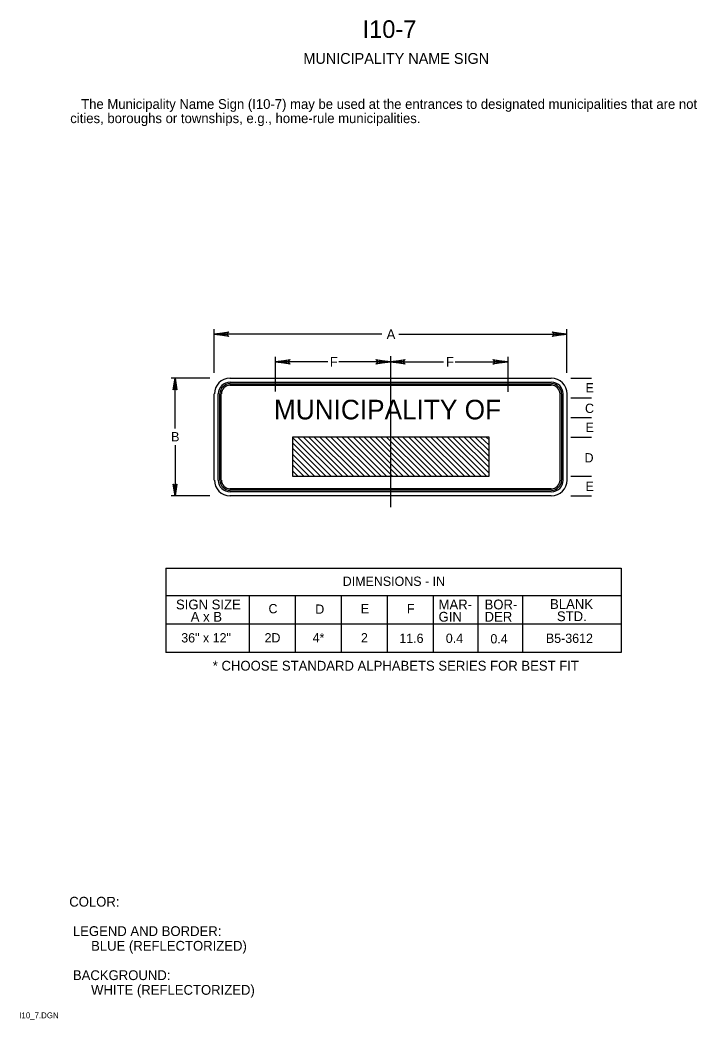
# Model space of a CAD drawing. Extents: x 0.013 to 0.185, y 0.004 to 0.259.
import ezdxf

# ---------------------------------------------------------------- set-up
doc = ezdxf.new("R2010")
doc.units = 0
for name, color, linetype in [('1', 7, 'Continuous'), ('2', 7, 'Continuous'), ('3', 7, 'Continuous')]:
    doc.layers.add(name, color=color, linetype=linetype)

# ---------------------------------------------------------------- blocks, each defined once
blk = doc.blocks.new('RARROW')
at = {"layer": '3'}
for p, q in [((-2.156, 0.285), (-2.2665, 0.384625)), ((-2.2665, 0.384625), (0, 0)), ((0, 0), (-2.2665, -0.379125)), ((-2.156, 0.285), (-2.075625, 0.12075)), ((0, 0), (-2.156, 0.285)), ((-2.14975, -0.2705), (0, 0)), ((-2.075625, 0.12075), (0, 0)), ((0, 0), (-2.074, -0.108)), ((-2.2665, -0.379125), (-2.14975, -0.2705)), ((-2.074, -0.108), (-2.14975, -0.2705))]:
    blk.add_line(p, q, dxfattribs=at)

msp = doc.modelspace()

# ---------------------------------------------------------------- linework, layer by layer
at = {"layer": '1'}
msp.add_line((0.10712, 0.17336), (0.10712, 0.13487), dxfattribs=at)
at = {"layer": '3'}
for p, q in [((0.06212, 0.16917), (0.06212, 0.18025)), ((0.10487, 0.179), (0.06212, 0.179)), ((0.10925, 0.179), (0.15213, 0.179)), ((0.15213, 0.16917), (0.15213, 0.18025)), ((0.07776, 0.16435), (0.07776, 0.17319)), ((0.09112, 0.17194), (0.07776, 0.17194)), ((0.10712, 0.17194), (0.0939, 0.17194)), ((0.10712, 0.17194), (0.10712, 0.17069)), ((0.10712, 0.17194), (0.12062, 0.17194)), ((0.12359, 0.17194), (0.13712, 0.17194)), ((0.13712, 0.16425), (0.13712, 0.17319)), ((0.06097, 0.16775), (0.05113, 0.16775)), ((0.05212, 0.15488), (0.05212, 0.16775)), ((0.06613, 0.16775), (0.14813, 0.16775)), ((0.06613, 0.16675), (0.14813, 0.16675)), ((0.06613, 0.16635), (0.14813, 0.16635)), ((0.06613, 0.16595), (0.14813, 0.16595)), ((0.15313, 0.16775), (0.15838, 0.16775)), ((0.06212, 0.14175), (0.06212, 0.16375)), ((0.06313, 0.14175), (0.06313, 0.16375)), ((0.06352, 0.14175), (0.06352, 0.16375)), ((0.06392, 0.14175), (0.06392, 0.16375)), ((0.15032, 0.16375), (0.15032, 0.14175)), ((0.15072, 0.16375), (0.15072, 0.14175)), ((0.15113, 0.16375), (0.15113, 0.14175)), ((0.15213, 0.16375), (0.15213, 0.14175)), ((0.15313, 0.16275), (0.15838, 0.16275)), ((0.15313, 0.15775), (0.15838, 0.15775)), ((0.05212, 0.15063), (0.05212, 0.13775)), ((0.08213, 0.15263), (0.092, 0.14275)), ((0.08213, 0.15125), (0.09062, 0.14275)), ((0.0835, 0.15275), (0.0935, 0.14275)), ((0.08488, 0.15275), (0.09488, 0.14275)), ((0.08625, 0.15275), (0.09625, 0.14275)), ((0.08763, 0.15275), (0.09763, 0.14275)), ((0.08912, 0.15275), (0.09913, 0.14275)), ((0.0905, 0.15275), (0.1005, 0.14275)), ((0.09187, 0.15275), (0.10188, 0.14275)), ((0.09337, 0.15275), (0.10338, 0.14275)), ((0.09475, 0.15275), (0.10475, 0.14275)), ((0.09613, 0.15275), (0.10612, 0.14275)), ((0.09763, 0.15275), (0.10762, 0.14275)), ((0.099, 0.15275), (0.109, 0.14275)), ((0.10038, 0.15275), (0.11038, 0.14275)), ((0.10188, 0.15275), (0.11188, 0.14275)), ((0.10325, 0.15275), (0.11325, 0.14275)), ((0.10462, 0.15275), (0.11463, 0.14275)), ((0.10612, 0.15275), (0.11613, 0.14275)), ((0.1075, 0.15275), (0.1175, 0.14275)), ((0.10887, 0.15275), (0.11888, 0.14275)), ((0.11025, 0.15275), (0.12025, 0.14275)), ((0.11175, 0.15275), (0.12175, 0.14275)), ((0.11313, 0.15275), (0.12312, 0.14275)), ((0.1145, 0.15275), (0.1245, 0.14275)), ((0.116, 0.15275), (0.126, 0.14275)), ((0.11738, 0.15275), (0.12738, 0.14275)), ((0.11875, 0.15275), (0.12875, 0.14275)), ((0.12025, 0.15275), (0.13025, 0.14275)), ((0.12162, 0.15275), (0.13162, 0.14275)), ((0.123, 0.15275), (0.13225, 0.1435)), ((0.1245, 0.15275), (0.13225, 0.145)), ((0.12588, 0.15275), (0.13225, 0.14638)), ((0.12725, 0.15275), (0.13225, 0.14775)), ((0.12875, 0.15275), (0.13225, 0.14925)), ((0.13012, 0.15275), (0.13225, 0.15063)), ((0.1315, 0.15275), (0.13225, 0.152)), ((0.15313, 0.15275), (0.15838, 0.15275)), ((0.08213, 0.14988), (0.08925, 0.14275)), ((0.08213, 0.14838), (0.08775, 0.14275)), ((0.08213, 0.147), (0.08638, 0.14275)), ((0.08213, 0.14563), (0.085, 0.14275)), ((0.08213, 0.14413), (0.0835, 0.14275)), ((0.08213, 0.14275), (0.08213, 0.14275)), ((0.15313, 0.14275), (0.15838, 0.14275)), ((0.14813, 0.13955), (0.06613, 0.13955)), ((0.14813, 0.13915), (0.06613, 0.13915)), ((0.14813, 0.13875), (0.06613, 0.13875)), ((0.06097, 0.13775), (0.05113, 0.13775)), ((0.14813, 0.13775), (0.06613, 0.13775)), ((0.15313, 0.13775), (0.15838, 0.13775)), ((0.04975, 0.11925), (0.166, 0.11925)), ((0.04975, 0.11925), (0.04975, 0.09775)), ((0.166, 0.11925), (0.166, 0.09775)), ((0.07104, 0.11235), (0.07104, 0.09772)), ((0.166, 0.11225), (0.04975, 0.11225)), ((0.08275, 0.11225), (0.08275, 0.09775)), ((0.0945, 0.11225), (0.0945, 0.09775)), ((0.10625, 0.11225), (0.10625, 0.09775)), ((0.11804, 0.11223), (0.11804, 0.09772)), ((0.12941, 0.11223), (0.12941, 0.09772)), ((0.14079, 0.11223), (0.14079, 0.09772)), ((0.166, 0.105), (0.04975, 0.105)), ((0.166, 0.09775), (0.04975, 0.09775))]:
    msp.add_line(p, q, dxfattribs=at)
msp.add_lwpolyline([(0.13225, 0.15275), (0.08213, 0.15275), (0.08213, 0.14275), (0.13225, 0.14275)], close=True, dxfattribs=at)
for centre, radius, start, end in [((0.06617, 0.16375), 0.004, 90, 180), ((0.06617, 0.16375), 0.003, 90, 180), ((0.06617, 0.16375), 0.0026, 90, 180), ((0.06617, 0.16375), 0.0022, 90, 180), ((0.14817, 0.16375), 0.004, 0, 90), ((0.14817, 0.16375), 0.003, 0, 90), ((0.14817, 0.16375), 0.0026, 0, 90), ((0.14817, 0.16375), 0.0022, 0, 90), ((0.06617, 0.14175), 0.004, 180, 270), ((0.06617, 0.14175), 0.003, 180, 270), ((0.06617, 0.14175), 0.0026, 180, 270), ((0.06617, 0.14175), 0.0022, 180, 270), ((0.14817, 0.14175), 0.004, 270, 0), ((0.14817, 0.14175), 0.003, 270, 0), ((0.14817, 0.14175), 0.0026, 270, 0), ((0.14817, 0.14175), 0.0022, 270, 0)]:
    msp.add_arc(centre, radius, start, end, dxfattribs=at)

# ---------------------------------------------------------------- block references
for p, xscale, yscale, rotation in [((0.06212, 0.179), 0.0016545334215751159, 0.0016366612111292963, 180), ((0.07775, 0.17194), 0.0016545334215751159, 0.0016366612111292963, 180), ((0.10712, 0.17194), 0.0016545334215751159, 0.0016366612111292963, 180), ((0.05212, 0.16775), 0.0013236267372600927, 0.001309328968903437, 90), ((0.05212, 0.13775), 0.0013236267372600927, 0.001309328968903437, -90)]:
    msp.add_blockref('RARROW', p, dxfattribs=dict(at, xscale=xscale, yscale=yscale, rotation=rotation))
at = {"layer": '3', "xscale": 0.0016545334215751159, "yscale": 0.0016366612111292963}
for p in [(0.15213, 0.179), (0.10712, 0.17194), (0.137, 0.17194)]:
    msp.add_blockref('RARROW', p, dxfattribs=at)

# ---------------------------------------------------------------- texts
at = {"layer": '1'}
for s, height, p in [('I10-7', 0.0045, (0.1, 0.25462)), ('MUNICIPALITY NAME SIGN', 0.0027503, (0.08488, 0.248)), ('COLOR:', 0.0025, (0.02513, 0.03288)), (' LEGEND AND BORDER:', 0.0024998, (0.02513, 0.02538)), ('      BLUE (REFLECTORIZED)', 0.0024998, (0.02513, 0.02163)), (' BACKGROUND:', 0.0024998, (0.02513, 0.01413)), ('      WHITE (REFLECTORIZED)', 0.0024998, (0.02513, 0.01038)), ('I10_7.DGN', 0.0015, (0.01238, 0.00438))]:
    msp.add_text(s, height=height, dxfattribs=at).set_placement(p)
at = {"layer": '2'}
for s, height, p in [('   The Municipality Name Sign (I10-7) may be used at the entrances to designated municipalities that are not', 0.00249975, (0.02538, 0.2365)), ('cities, boroughs or townships, e.g., home-rule municipalities.', 0.0024998, (0.02538, 0.23287))]:
    msp.add_text(s, height=height, dxfattribs=at).set_placement(p)
at = {"layer": '3'}
for s, height, p in [('A', 0.0025, (0.10612, 0.17775)), ('F', 0.0025, (0.09162, 0.17069)), ('F', 0.0025, (0.12125, 0.17069)), ('E', 0.00238, (0.15688, 0.16412)), ('MUNICIPALITY OF', 0.0050003, (0.07737, 0.15725)), ('C', 0.00238, (0.15675, 0.15888)), ('E', 0.00238, (0.15688, 0.154)), ('B', 0.00238, (0.05113, 0.15163)), ('D', 0.00238, (0.15663, 0.14625)), ('E', 0.00238, (0.15688, 0.139)), ('DIMENSIONS - IN', 0.0023752, (0.09492, 0.11475)), ('SIGN SIZE', 0.0025, (0.05237, 0.10875)), ('C', 0.00238, (0.07598, 0.10775)), ('D', 0.00238, (0.08791, 0.10762)), ('E', 0.00238, (0.09952, 0.10775)), ('F', 0.00238, (0.11131, 0.10775)), ('MAR-', 0.0025, (0.11938, 0.10875)), ('BOR-', 0.0025, (0.13112, 0.10875)), ('BLANK', 0.0025, (0.14783, 0.10887)), ('A x B', 0.0025, (0.05613, 0.10562)), ('GIN', 0.0025, (0.11938, 0.10562)), ('DER', 0.0025, (0.13112, 0.10562)), ('STD.', 0.0025, (0.14958, 0.10575)), ('36" x 12"', 0.002375, (0.05371, 0.10031)), ('2D', 0.002375, (0.07497, 0.10031)), ('4*', 0.002375, (0.08724, 0.10031)), ('2', 0.00238, (0.09956, 0.10031)), ('11.6', 0.002375, (0.10936, 0.10019)), ('0.4', 0.002375, (0.12123, 0.10019)), ('0.4', 0.002375, (0.13261, 0.10006)), ('B5-3612', 0.002375, (0.14677, 0.10019)), ('* CHOOSE STANDARD ALPHABETS SERIES FOR BEST FIT', 0.0024998, (0.06175, 0.09312))]:
    msp.add_text(s, height=height, dxfattribs=at).set_placement(p)

doc.saveas('drawing.dxf')
